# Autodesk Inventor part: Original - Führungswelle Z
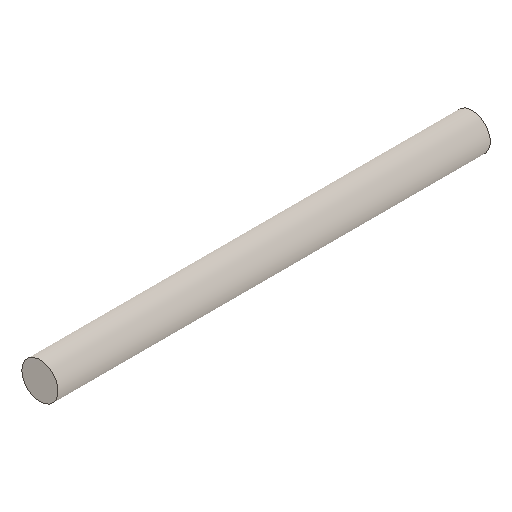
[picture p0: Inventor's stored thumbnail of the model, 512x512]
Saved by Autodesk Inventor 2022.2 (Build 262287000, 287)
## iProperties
Created: 2024-09
Part Number: Original - Führungswelle Z
Material: Generico
Document SubType Name: Modeling
Designer: 18907419
Density: 1 g/cm^3
Appearance: Default
Author: 18907419
Revision Number: ANY
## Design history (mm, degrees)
feature "Aufsatz-Linear austragen1"
node "Solido1"
